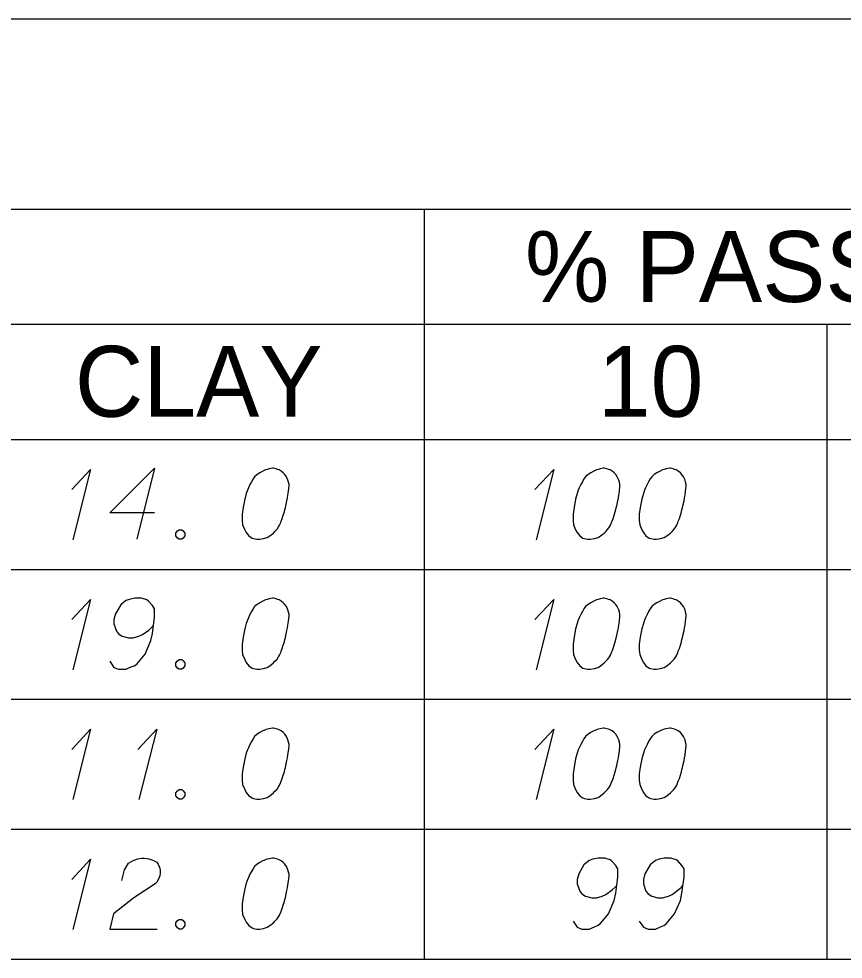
# Model space of a CAD drawing. Extents: x 2074207 to 2076812, y 516372 to 523312.
# Drawn here: x 2076622.7 to 2076678.5, y 516953.6 to 517017.2 of the extents above; entities that cross this region are included whole.
import ezdxf

# ---------------------------------------------------------------- set-up
doc = ezdxf.new("R2010")
doc.units = 0
for name, color, linetype in [('Prop DirtTable_ Soil Test Results - Outline (Major)', 7, 'Continuous'), ('Prop DirtTable_ Soil Test Results - Outline (Minor)', 7, 'Continuous'), ('Prop DirtTable_ Soil Test Results - Tx (Header - Small)', 7, 'Continuous'), ('Prop DirtTable_ Soil Test Results - Tx (Sample Data)', 7, 'Continuous')]:
    doc.layers.add(name, color=color, linetype=linetype)

msp = doc.modelspace()

# ---------------------------------------------------------------- linework, layer by layer
at = {"layer": 'Prop DirtTable_ Soil Test Results - Outline (Major)'}
for p, q in [((2076260.609, 517017.246), (2076811.903, 517017.246)), ((2076260.609, 516988.761), (2076811.903, 516988.761)), ((2076260.609, 516988.761), (2076811.903, 516988.761)), ((2076260.609, 516953.561), (2076811.903, 516953.561))]:
    msp.add_line(p, q, dxfattribs=at)
at = {"layer": 'Prop DirtTable_ Soil Test Results - Outline (Minor)'}
for p, q in [((2076260.609, 517004.361), (2076811.903, 517004.361)), ((2076650.154, 517004.361), (2076650.154, 516979.961)), ((2076526.074, 516996.561), (2076731.93, 516996.561)), ((2076677.413, 516996.561), (2076677.413, 516979.961)), ((2076260.609, 516979.961), (2076811.903, 516979.961)), ((2076260.609, 516979.961), (2076811.903, 516979.961)), ((2076650.154, 516979.961), (2076650.154, 516971.161)), ((2076677.413, 516979.961), (2076677.413, 516971.161)), ((2076260.609, 516971.161), (2076811.903, 516971.161)), ((2076260.609, 516971.161), (2076811.903, 516971.161)), ((2076650.154, 516971.161), (2076650.154, 516962.361)), ((2076677.413, 516971.161), (2076677.413, 516962.361)), ((2076260.609, 516962.361), (2076811.903, 516962.361)), ((2076260.609, 516962.361), (2076811.903, 516962.361)), ((2076650.154, 516962.361), (2076650.154, 516953.561)), ((2076677.413, 516962.361), (2076677.413, 516953.561)), ((2076260.609, 516953.561), (2076811.903, 516953.561))]:
    msp.add_line(p, q, dxfattribs=at)
at = {"layer": 'Prop DirtTable_ Soil Test Results - Tx (Sample Data)'}
for points in [[(2076626.3, 516985.369), (2076627.57, 516986.73), (2076626.371, 516981.967)], [(2076631.909, 516983.782), (2076628.876, 516983.782), (2076631.909, 516986.805), (2076630.71, 516982.005)], [(2076639.952, 516986.805), (2076639.882, 516986.805), (2076639.67, 516986.767), (2076639.529, 516986.73), (2076639.423, 516986.692), (2076639.247, 516986.616), (2076639.035, 516986.503), (2076638.859, 516986.389), (2076638.682, 516986.238), (2076638.576, 516986.087), (2076638.471, 516985.898), (2076638.365, 516985.709), (2076638.259, 516985.482), (2076638.188, 516985.331), (2076638.118, 516985.104), (2076638.012, 516984.726), (2076637.906, 516984.159), (2076637.836, 516983.706), (2076637.836, 516983.29), (2076637.871, 516982.988), (2076638.012, 516982.648), (2076638.118, 516982.459), (2076638.294, 516982.232), (2076638.506, 516982.081), (2076638.612, 516982.043), (2076638.823, 516982.005), (2076639, 516982.005), (2076639.282, 516982.043), (2076639.529, 516982.119), (2076639.705, 516982.232), (2076639.952, 516982.421), (2076640.058, 516982.534), (2076640.199, 516982.685), (2076640.305, 516982.837), (2076640.375, 516982.95), (2076640.446, 516983.139), (2076640.481, 516983.215), (2076640.552, 516983.404), (2076640.622, 516983.63), (2076640.693, 516983.857), (2076640.728, 516984.008), (2076640.763, 516984.122), (2076640.799, 516984.273), (2076640.869, 516984.613), (2076640.905, 516984.802), (2076640.94, 516984.991), (2076640.975, 516985.256), (2076641.01, 516985.596), (2076641.01, 516985.709), (2076640.975, 516985.86), (2076640.94, 516986.011), (2076640.834, 516986.238), (2076640.728, 516986.389), (2076640.622, 516986.503), (2076640.481, 516986.616), (2076640.34, 516986.692), (2076640.234, 516986.73), (2076640.129, 516986.767), (2076639.952, 516986.805)], [(2076657.66, 516985.369), (2076658.93, 516986.73), (2076657.731, 516981.967)], [(2076662.352, 516986.805), (2076662.282, 516986.805), (2076662.07, 516986.767), (2076661.929, 516986.73), (2076661.823, 516986.692), (2076661.647, 516986.616), (2076661.435, 516986.503), (2076661.259, 516986.389), (2076661.082, 516986.238), (2076660.976, 516986.087), (2076660.871, 516985.898), (2076660.765, 516985.709), (2076660.659, 516985.482), (2076660.588, 516985.331), (2076660.518, 516985.104), (2076660.412, 516984.726), (2076660.306, 516984.159), (2076660.236, 516983.706), (2076660.236, 516983.29), (2076660.271, 516982.988), (2076660.412, 516982.648), (2076660.518, 516982.459), (2076660.694, 516982.232), (2076660.906, 516982.081), (2076661.012, 516982.043), (2076661.223, 516982.005), (2076661.4, 516982.005), (2076661.682, 516982.043), (2076661.929, 516982.119), (2076662.105, 516982.232), (2076662.352, 516982.421), (2076662.458, 516982.534), (2076662.599, 516982.685), (2076662.705, 516982.837), (2076662.775, 516982.95), (2076662.846, 516983.139), (2076662.881, 516983.215), (2076662.952, 516983.404), (2076663.022, 516983.63), (2076663.093, 516983.857), (2076663.128, 516984.008), (2076663.163, 516984.122), (2076663.199, 516984.273), (2076663.269, 516984.613), (2076663.305, 516984.802), (2076663.34, 516984.991), (2076663.375, 516985.256), (2076663.41, 516985.596), (2076663.41, 516985.709), (2076663.375, 516985.86), (2076663.34, 516986.011), (2076663.234, 516986.238), (2076663.128, 516986.389), (2076663.022, 516986.503), (2076662.881, 516986.616), (2076662.74, 516986.692), (2076662.634, 516986.73), (2076662.529, 516986.767), (2076662.352, 516986.805)], [(2076666.832, 516986.805), (2076666.762, 516986.805), (2076666.55, 516986.767), (2076666.409, 516986.73), (2076666.303, 516986.692), (2076666.127, 516986.616), (2076665.915, 516986.503), (2076665.739, 516986.389), (2076665.562, 516986.238), (2076665.456, 516986.087), (2076665.351, 516985.898), (2076665.245, 516985.709), (2076665.139, 516985.482), (2076665.068, 516985.331), (2076664.998, 516985.104), (2076664.892, 516984.726), (2076664.786, 516984.159), (2076664.716, 516983.706), (2076664.716, 516983.29), (2076664.751, 516982.988), (2076664.892, 516982.648), (2076664.998, 516982.459), (2076665.174, 516982.232), (2076665.386, 516982.081), (2076665.492, 516982.043), (2076665.703, 516982.005), (2076665.88, 516982.005), (2076666.162, 516982.043), (2076666.409, 516982.119), (2076666.585, 516982.232), (2076666.832, 516982.421), (2076666.938, 516982.534), (2076667.079, 516982.685), (2076667.185, 516982.837), (2076667.255, 516982.95), (2076667.326, 516983.139), (2076667.361, 516983.215), (2076667.432, 516983.404), (2076667.502, 516983.63), (2076667.573, 516983.857), (2076667.608, 516984.008), (2076667.643, 516984.122), (2076667.679, 516984.273), (2076667.749, 516984.613), (2076667.785, 516984.802), (2076667.82, 516984.991), (2076667.855, 516985.256), (2076667.89, 516985.596), (2076667.89, 516985.709), (2076667.855, 516985.86), (2076667.82, 516986.011), (2076667.714, 516986.238), (2076667.608, 516986.389), (2076667.502, 516986.503), (2076667.361, 516986.616), (2076667.22, 516986.692), (2076667.114, 516986.73), (2076667.009, 516986.767), (2076666.832, 516986.805)], [(2076633.567, 516982.648), (2076633.744, 516982.648), (2076633.849, 516982.572), (2076633.955, 516982.421), (2076633.955, 516982.232), (2076633.849, 516982.081), (2076633.744, 516982.005), (2076633.567, 516982.005), (2076633.461, 516982.081), (2076633.356, 516982.232), (2076633.356, 516982.421), (2076633.461, 516982.572), (2076633.567, 516982.648)], [(2076626.3, 516976.569), (2076627.57, 516977.93), (2076626.371, 516973.167)], [(2076628.876, 516973.734), (2076629.158, 516973.319), (2076629.475, 516973.205), (2076629.969, 516973.205), (2076630.322, 516973.356), (2076630.534, 516973.432), (2076630.71, 516973.545), (2076631.274, 516974.226), (2076631.662, 516975.133), (2076631.768, 516975.624), (2076631.909, 516976.72), (2076631.909, 516977.287), (2076631.768, 516977.514), (2076631.486, 516977.816), (2076631.38, 516977.892), (2076631.027, 516978.005), (2076630.569, 516978.005), (2076630.216, 516977.93), (2076629.969, 516977.854), (2076629.616, 516977.552), (2076629.264, 516976.947), (2076629.158, 516976.569), (2076629.158, 516976.267), (2076629.334, 516975.775), (2076629.475, 516975.586), (2076629.722, 516975.435), (2076630.146, 516975.322), (2076630.463, 516975.322), (2076630.851, 516975.435), (2076631.098, 516975.548), (2076631.521, 516975.851), (2076631.733, 516976.04), (2076631.839, 516976.153)], [(2076639.952, 516978.005), (2076639.882, 516978.005), (2076639.67, 516977.967), (2076639.529, 516977.93), (2076639.423, 516977.892), (2076639.247, 516977.816), (2076639.035, 516977.703), (2076638.859, 516977.589), (2076638.682, 516977.438), (2076638.576, 516977.287), (2076638.471, 516977.098), (2076638.365, 516976.909), (2076638.259, 516976.682), (2076638.188, 516976.531), (2076638.118, 516976.304), (2076638.012, 516975.926), (2076637.906, 516975.359), (2076637.836, 516974.906), (2076637.836, 516974.49), (2076637.871, 516974.188), (2076638.012, 516973.848), (2076638.118, 516973.659), (2076638.294, 516973.432), (2076638.506, 516973.281), (2076638.612, 516973.243), (2076638.823, 516973.205), (2076639, 516973.205), (2076639.282, 516973.243), (2076639.529, 516973.319), (2076639.705, 516973.432), (2076639.952, 516973.621), (2076640.058, 516973.734), (2076640.199, 516973.885), (2076640.305, 516974.037), (2076640.375, 516974.15), (2076640.446, 516974.339), (2076640.481, 516974.415), (2076640.552, 516974.604), (2076640.622, 516974.83), (2076640.693, 516975.057), (2076640.728, 516975.208), (2076640.763, 516975.322), (2076640.799, 516975.473), (2076640.869, 516975.813), (2076640.905, 516976.002), (2076640.94, 516976.191), (2076640.975, 516976.456), (2076641.01, 516976.796), (2076641.01, 516976.909), (2076640.975, 516977.06), (2076640.94, 516977.211), (2076640.834, 516977.438), (2076640.728, 516977.589), (2076640.622, 516977.703), (2076640.481, 516977.816), (2076640.34, 516977.892), (2076640.234, 516977.93), (2076640.129, 516977.967), (2076639.952, 516978.005)], [(2076657.66, 516976.569), (2076658.93, 516977.93), (2076657.731, 516973.167)], [(2076662.352, 516978.005), (2076662.282, 516978.005), (2076662.07, 516977.967), (2076661.929, 516977.93), (2076661.823, 516977.892), (2076661.647, 516977.816), (2076661.435, 516977.703), (2076661.259, 516977.589), (2076661.082, 516977.438), (2076660.976, 516977.287), (2076660.871, 516977.098), (2076660.765, 516976.909), (2076660.659, 516976.682), (2076660.588, 516976.531), (2076660.518, 516976.304), (2076660.412, 516975.926), (2076660.306, 516975.359), (2076660.236, 516974.906), (2076660.236, 516974.49), (2076660.271, 516974.188), (2076660.412, 516973.848), (2076660.518, 516973.659), (2076660.694, 516973.432), (2076660.906, 516973.281), (2076661.012, 516973.243), (2076661.223, 516973.205), (2076661.4, 516973.205), (2076661.682, 516973.243), (2076661.929, 516973.319), (2076662.105, 516973.432), (2076662.352, 516973.621), (2076662.458, 516973.734), (2076662.599, 516973.885), (2076662.705, 516974.037), (2076662.775, 516974.15), (2076662.846, 516974.339), (2076662.881, 516974.415), (2076662.952, 516974.604), (2076663.022, 516974.83), (2076663.093, 516975.057), (2076663.128, 516975.208), (2076663.163, 516975.322), (2076663.199, 516975.473), (2076663.269, 516975.813), (2076663.305, 516976.002), (2076663.34, 516976.191), (2076663.375, 516976.456), (2076663.41, 516976.796), (2076663.41, 516976.909), (2076663.375, 516977.06), (2076663.34, 516977.211), (2076663.234, 516977.438), (2076663.128, 516977.589), (2076663.022, 516977.703), (2076662.881, 516977.816), (2076662.74, 516977.892), (2076662.634, 516977.93), (2076662.529, 516977.967), (2076662.352, 516978.005)], [(2076666.832, 516978.005), (2076666.762, 516978.005), (2076666.55, 516977.967), (2076666.409, 516977.93), (2076666.303, 516977.892), (2076666.127, 516977.816), (2076665.915, 516977.703), (2076665.739, 516977.589), (2076665.562, 516977.438), (2076665.456, 516977.287), (2076665.351, 516977.098), (2076665.245, 516976.909), (2076665.139, 516976.682), (2076665.068, 516976.531), (2076664.998, 516976.304), (2076664.892, 516975.926), (2076664.786, 516975.359), (2076664.716, 516974.906), (2076664.716, 516974.49), (2076664.751, 516974.188), (2076664.892, 516973.848), (2076664.998, 516973.659), (2076665.174, 516973.432), (2076665.386, 516973.281), (2076665.492, 516973.243), (2076665.703, 516973.205), (2076665.88, 516973.205), (2076666.162, 516973.243), (2076666.409, 516973.319), (2076666.585, 516973.432), (2076666.832, 516973.621), (2076666.938, 516973.734), (2076667.079, 516973.885), (2076667.185, 516974.037), (2076667.255, 516974.15), (2076667.326, 516974.339), (2076667.361, 516974.415), (2076667.432, 516974.604), (2076667.502, 516974.83), (2076667.573, 516975.057), (2076667.608, 516975.208), (2076667.643, 516975.322), (2076667.679, 516975.473), (2076667.749, 516975.813), (2076667.785, 516976.002), (2076667.82, 516976.191), (2076667.855, 516976.456), (2076667.89, 516976.796), (2076667.89, 516976.909), (2076667.855, 516977.06), (2076667.82, 516977.211), (2076667.714, 516977.438), (2076667.608, 516977.589), (2076667.502, 516977.703), (2076667.361, 516977.816), (2076667.22, 516977.892), (2076667.114, 516977.93), (2076667.009, 516977.967), (2076666.832, 516978.005)], [(2076633.567, 516973.848), (2076633.744, 516973.848), (2076633.849, 516973.772), (2076633.955, 516973.621), (2076633.955, 516973.432), (2076633.849, 516973.281), (2076633.744, 516973.205), (2076633.567, 516973.205), (2076633.461, 516973.281), (2076633.356, 516973.432), (2076633.356, 516973.621), (2076633.461, 516973.772), (2076633.567, 516973.848)], [(2076626.3, 516967.769), (2076627.57, 516969.13), (2076626.371, 516964.367)], [(2076630.78, 516967.769), (2076632.05, 516969.13), (2076630.851, 516964.367)], [(2076639.952, 516969.205), (2076639.882, 516969.205), (2076639.67, 516969.167), (2076639.529, 516969.13), (2076639.423, 516969.092), (2076639.247, 516969.016), (2076639.035, 516968.903), (2076638.859, 516968.789), (2076638.682, 516968.638), (2076638.576, 516968.487), (2076638.471, 516968.298), (2076638.365, 516968.109), (2076638.259, 516967.882), (2076638.188, 516967.731), (2076638.118, 516967.504), (2076638.012, 516967.126), (2076637.906, 516966.559), (2076637.836, 516966.106), (2076637.836, 516965.69), (2076637.871, 516965.388), (2076638.012, 516965.048), (2076638.118, 516964.859), (2076638.294, 516964.632), (2076638.506, 516964.481), (2076638.612, 516964.443), (2076638.823, 516964.405), (2076639, 516964.405), (2076639.282, 516964.443), (2076639.529, 516964.519), (2076639.705, 516964.632), (2076639.952, 516964.821), (2076640.058, 516964.934), (2076640.199, 516965.085), (2076640.305, 516965.237), (2076640.375, 516965.35), (2076640.446, 516965.539), (2076640.481, 516965.615), (2076640.552, 516965.804), (2076640.622, 516966.03), (2076640.693, 516966.257), (2076640.728, 516966.408), (2076640.763, 516966.522), (2076640.799, 516966.673), (2076640.869, 516967.013), (2076640.905, 516967.202), (2076640.94, 516967.391), (2076640.975, 516967.656), (2076641.01, 516967.996), (2076641.01, 516968.109), (2076640.975, 516968.26), (2076640.94, 516968.411), (2076640.834, 516968.638), (2076640.728, 516968.789), (2076640.622, 516968.903), (2076640.481, 516969.016), (2076640.34, 516969.092), (2076640.234, 516969.13), (2076640.129, 516969.167), (2076639.952, 516969.205)], [(2076657.66, 516967.769), (2076658.93, 516969.13), (2076657.731, 516964.367)], [(2076662.352, 516969.205), (2076662.282, 516969.205), (2076662.07, 516969.167), (2076661.929, 516969.13), (2076661.823, 516969.092), (2076661.647, 516969.016), (2076661.435, 516968.903), (2076661.259, 516968.789), (2076661.082, 516968.638), (2076660.976, 516968.487), (2076660.871, 516968.298), (2076660.765, 516968.109), (2076660.659, 516967.882), (2076660.588, 516967.731), (2076660.518, 516967.504), (2076660.412, 516967.126), (2076660.306, 516966.559), (2076660.236, 516966.106), (2076660.236, 516965.69), (2076660.271, 516965.388), (2076660.412, 516965.048), (2076660.518, 516964.859), (2076660.694, 516964.632), (2076660.906, 516964.481), (2076661.012, 516964.443), (2076661.223, 516964.405), (2076661.4, 516964.405), (2076661.682, 516964.443), (2076661.929, 516964.519), (2076662.105, 516964.632), (2076662.352, 516964.821), (2076662.458, 516964.934), (2076662.599, 516965.085), (2076662.705, 516965.237), (2076662.775, 516965.35), (2076662.846, 516965.539), (2076662.881, 516965.615), (2076662.952, 516965.804), (2076663.022, 516966.03), (2076663.093, 516966.257), (2076663.128, 516966.408), (2076663.163, 516966.522), (2076663.199, 516966.673), (2076663.269, 516967.013), (2076663.305, 516967.202), (2076663.34, 516967.391), (2076663.375, 516967.656), (2076663.41, 516967.996), (2076663.41, 516968.109), (2076663.375, 516968.26), (2076663.34, 516968.411), (2076663.234, 516968.638), (2076663.128, 516968.789), (2076663.022, 516968.903), (2076662.881, 516969.016), (2076662.74, 516969.092), (2076662.634, 516969.13), (2076662.529, 516969.167), (2076662.352, 516969.205)], [(2076666.832, 516969.205), (2076666.762, 516969.205), (2076666.55, 516969.167), (2076666.409, 516969.13), (2076666.303, 516969.092), (2076666.127, 516969.016), (2076665.915, 516968.903), (2076665.739, 516968.789), (2076665.562, 516968.638), (2076665.456, 516968.487), (2076665.351, 516968.298), (2076665.245, 516968.109), (2076665.139, 516967.882), (2076665.068, 516967.731), (2076664.998, 516967.504), (2076664.892, 516967.126), (2076664.786, 516966.559), (2076664.716, 516966.106), (2076664.716, 516965.69), (2076664.751, 516965.388), (2076664.892, 516965.048), (2076664.998, 516964.859), (2076665.174, 516964.632), (2076665.386, 516964.481), (2076665.492, 516964.443), (2076665.703, 516964.405), (2076665.88, 516964.405), (2076666.162, 516964.443), (2076666.409, 516964.519), (2076666.585, 516964.632), (2076666.832, 516964.821), (2076666.938, 516964.934), (2076667.079, 516965.085), (2076667.185, 516965.237), (2076667.255, 516965.35), (2076667.326, 516965.539), (2076667.361, 516965.615), (2076667.432, 516965.804), (2076667.502, 516966.03), (2076667.573, 516966.257), (2076667.608, 516966.408), (2076667.643, 516966.522), (2076667.679, 516966.673), (2076667.749, 516967.013), (2076667.785, 516967.202), (2076667.82, 516967.391), (2076667.855, 516967.656), (2076667.89, 516967.996), (2076667.89, 516968.109), (2076667.855, 516968.26), (2076667.82, 516968.411), (2076667.714, 516968.638), (2076667.608, 516968.789), (2076667.502, 516968.903), (2076667.361, 516969.016), (2076667.22, 516969.092), (2076667.114, 516969.13), (2076667.009, 516969.167), (2076666.832, 516969.205)], [(2076633.567, 516965.048), (2076633.744, 516965.048), (2076633.849, 516964.972), (2076633.955, 516964.821), (2076633.955, 516964.632), (2076633.849, 516964.481), (2076633.744, 516964.405), (2076633.567, 516964.405), (2076633.461, 516964.481), (2076633.356, 516964.632), (2076633.356, 516964.821), (2076633.461, 516964.972), (2076633.567, 516965.048)], [(2076626.3, 516958.969), (2076627.57, 516960.33), (2076626.371, 516955.567)], [(2076629.687, 516958.893), (2076629.863, 516959.611), (2076630.146, 516960.065), (2076630.463, 516960.254), (2076630.78, 516960.367), (2076631.027, 516960.405), (2076631.204, 516960.405), (2076631.521, 516960.367), (2076631.733, 516960.292), (2076631.839, 516960.254), (2076632.05, 516960.141), (2076632.156, 516959.989), (2076632.227, 516959.838), (2076632.262, 516959.725), (2076632.297, 516959.574), (2076632.297, 516959.385), (2076632.262, 516959.196), (2076632.227, 516959.082), (2076632.156, 516958.931), (2076632.05, 516958.78), (2076631.945, 516958.667), (2076630.498, 516957.722), (2076629.123, 516956.626), (2076628.876, 516955.605), (2076632.086, 516955.605)], [(2076639.952, 516960.405), (2076639.882, 516960.405), (2076639.67, 516960.367), (2076639.529, 516960.33), (2076639.423, 516960.292), (2076639.247, 516960.216), (2076639.035, 516960.103), (2076638.859, 516959.989), (2076638.682, 516959.838), (2076638.576, 516959.687), (2076638.471, 516959.498), (2076638.365, 516959.309), (2076638.259, 516959.082), (2076638.188, 516958.931), (2076638.118, 516958.704), (2076638.012, 516958.326), (2076637.906, 516957.759), (2076637.836, 516957.306), (2076637.836, 516956.89), (2076637.871, 516956.588), (2076638.012, 516956.248), (2076638.118, 516956.059), (2076638.294, 516955.832), (2076638.506, 516955.681), (2076638.612, 516955.643), (2076638.823, 516955.605), (2076639, 516955.605), (2076639.282, 516955.643), (2076639.529, 516955.719), (2076639.705, 516955.832), (2076639.952, 516956.021), (2076640.058, 516956.134), (2076640.199, 516956.285), (2076640.305, 516956.437), (2076640.375, 516956.55), (2076640.446, 516956.739), (2076640.481, 516956.815), (2076640.552, 516957.004), (2076640.622, 516957.23), (2076640.693, 516957.457), (2076640.728, 516957.608), (2076640.763, 516957.722), (2076640.799, 516957.873), (2076640.869, 516958.213), (2076640.905, 516958.402), (2076640.94, 516958.591), (2076640.975, 516958.856), (2076641.01, 516959.196), (2076641.01, 516959.309), (2076640.975, 516959.46), (2076640.94, 516959.611), (2076640.834, 516959.838), (2076640.728, 516959.989), (2076640.622, 516960.103), (2076640.481, 516960.216), (2076640.34, 516960.292), (2076640.234, 516960.33), (2076640.129, 516960.367), (2076639.952, 516960.405)], [(2076660.236, 516956.134), (2076660.518, 516955.719), (2076660.835, 516955.605), (2076661.329, 516955.605), (2076661.682, 516955.756), (2076661.894, 516955.832), (2076662.07, 516955.945), (2076662.634, 516956.626), (2076663.022, 516957.533), (2076663.128, 516958.024), (2076663.269, 516959.12), (2076663.269, 516959.687), (2076663.128, 516959.914), (2076662.846, 516960.216), (2076662.74, 516960.292), (2076662.387, 516960.405), (2076661.929, 516960.405), (2076661.576, 516960.33), (2076661.329, 516960.254), (2076660.976, 516959.952), (2076660.624, 516959.347), (2076660.518, 516958.969), (2076660.518, 516958.667), (2076660.694, 516958.175), (2076660.835, 516957.986), (2076661.082, 516957.835), (2076661.506, 516957.722), (2076661.823, 516957.722), (2076662.211, 516957.835), (2076662.458, 516957.948), (2076662.881, 516958.251), (2076663.093, 516958.44), (2076663.199, 516958.553)], [(2076664.716, 516956.134), (2076664.998, 516955.719), (2076665.315, 516955.605), (2076665.809, 516955.605), (2076666.162, 516955.756), (2076666.374, 516955.832), (2076666.55, 516955.945), (2076667.114, 516956.626), (2076667.502, 516957.533), (2076667.608, 516958.024), (2076667.749, 516959.12), (2076667.749, 516959.687), (2076667.608, 516959.914), (2076667.326, 516960.216), (2076667.22, 516960.292), (2076666.867, 516960.405), (2076666.409, 516960.405), (2076666.056, 516960.33), (2076665.809, 516960.254), (2076665.456, 516959.952), (2076665.104, 516959.347), (2076664.998, 516958.969), (2076664.998, 516958.667), (2076665.174, 516958.175), (2076665.315, 516957.986), (2076665.562, 516957.835), (2076665.986, 516957.722), (2076666.303, 516957.722), (2076666.691, 516957.835), (2076666.938, 516957.948), (2076667.361, 516958.251), (2076667.573, 516958.44), (2076667.679, 516958.553)], [(2076633.567, 516956.248), (2076633.744, 516956.248), (2076633.849, 516956.172), (2076633.955, 516956.021), (2076633.955, 516955.832), (2076633.849, 516955.681), (2076633.744, 516955.605), (2076633.567, 516955.605), (2076633.461, 516955.681), (2076633.356, 516955.832), (2076633.356, 516956.021), (2076633.461, 516956.172), (2076633.567, 516956.248)]]:
    msp.add_lwpolyline(points, dxfattribs=at)

# ---------------------------------------------------------------- texts
at = {"layer": 'Prop DirtTable_ Soil Test Results - Tx (Header - Small)'}
for s, height, p in [('% PASSING (SIEVES)', 4.79998, (2076656.984, 516998.071)), ('CLAY', 4.8, (2076626.513, 516990.296)), ('10', 4.8, (2076661.92, 516990.296))]:
    msp.add_text(s, height=height, dxfattribs=at).set_placement(p)

doc.saveas('drawing.dxf')
